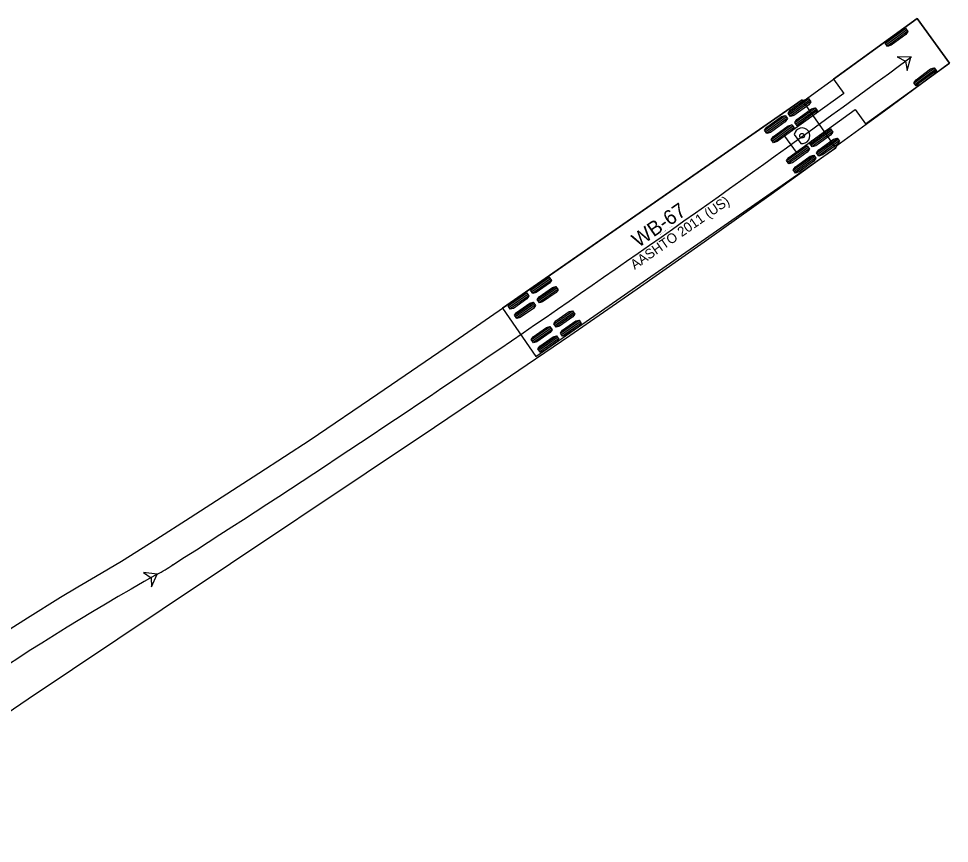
# Model space of a CAD drawing. Extents: x 2175591 to 2194071, y 76570 to 86955.
# Drawn here: x 2175817.3 to 2175952.4, y 76678.4 to 76798 of the extents above; entities that cross this region are included whole.
import ezdxf

# ---------------------------------------------------------------- set-up
doc = ezdxf.new("R2010")
doc.units = 0
doc.layers.add('C-UTIL-STRM-TEXT', color=7, linetype='Continuous')

msp = doc.modelspace()

# ---------------------------------------------------------------- linework, layer by layer
at = {"layer": 'C-UTIL-STRM-TEXT'}
for p, q in [((2175947.72, 76798.05), (2175935.56, 76789.26)), ((2175952.4, 76791.56), (2175947.72, 76798.05)), ((2175947.72, 76798.05), (2175947.72, 76798.05)), ((2175946.08, 76796.6), (2175943.13, 76794.43)), ((2175946.21, 76796.42), (2175943.26, 76794.24)), ((2175946.35, 76796.23), (2175943.4, 76794.06)), ((2175940.24, 76782.78), (2175952.4, 76791.56)), ((2175950.23, 76790.87), (2175947.28, 76788.69)), ((2175950.37, 76790.68), (2175947.42, 76788.5)), ((2175950.51, 76790.5), (2175947.55, 76788.32)), ((2175935.56, 76789.26), (2175937.06, 76787.18)), ((2175937.06, 76787.18), (2175928.47, 76780.98)), ((2175931.99, 76786.4), (2175929.02, 76784.26)), ((2175931.05, 76786.25), (2175887.52, 76756.01)), ((2175932.12, 76786.22), (2175929.15, 76784.07)), ((2175932.26, 76786.03), (2175929.29, 76783.89)), ((2175932.96, 76785.07), (2175929.98, 76782.92)), ((2175935.9, 76779.27), (2175931.05, 76786.25)), ((2175931.05, 76786.25), (2175931.05, 76786.25)), ((2175928.58, 76783.95), (2175925.61, 76781.8)), ((2175928.72, 76783.76), (2175925.75, 76781.61)), ((2175933.09, 76784.88), (2175930.12, 76782.73)), ((2175930.15, 76778.65), (2175938.74, 76784.86)), ((2175933.22, 76784.7), (2175930.25, 76782.55)), ((2175938.74, 76784.86), (2175940.24, 76782.78)), ((2175928.85, 76783.57), (2175925.88, 76781.43)), ((2175929.55, 76782.61), (2175926.58, 76780.46)), ((2175929.68, 76782.42), (2175926.71, 76780.28)), ((2175929.82, 76782.24), (2175926.85, 76780.09)), ((2175928.47, 76780.98), (2175930.15, 76778.65)), ((2175929.88, 76781.23), (2175930.83, 76779.92)), ((2175935.17, 76782), (2175932.2, 76779.85)), ((2175935.3, 76781.81), (2175932.33, 76779.67)), ((2175935.44, 76781.63), (2175932.47, 76779.48)), ((2175936.14, 76780.66), (2175933.16, 76778.52)), ((2175936.27, 76780.48), (2175933.3, 76778.33)), ((2175936.4, 76780.29), (2175933.43, 76778.14)), ((2175892.37, 76749.03), (2175935.9, 76779.27)), ((2175931.77, 76779.54), (2175928.79, 76777.39)), ((2175931.9, 76779.36), (2175928.93, 76777.21)), ((2175932.03, 76779.17), (2175929.06, 76777.02)), ((2175932.73, 76778.2), (2175929.76, 76776.06)), ((2175932.87, 76778.02), (2175929.89, 76775.87)), ((2175933, 76777.83), (2175930.03, 76775.68)), ((2175894.34, 76760.47), (2175891.63, 76758.59)), ((2175894.47, 76760.28), (2175891.76, 76758.4)), ((2175894.61, 76760.09), (2175891.9, 76758.21)), ((2175891.06, 76758.19), (2175888.35, 76756.3)), ((2175895.29, 76759.11), (2175892.58, 76757.23)), ((2175895.42, 76758.93), (2175892.71, 76757.04)), ((2175895.55, 76758.74), (2175892.84, 76756.86)), ((2175891.19, 76758), (2175888.48, 76756.12)), ((2175891.32, 76757.81), (2175888.61, 76755.93)), ((2175892, 76756.83), (2175889.29, 76754.95)), ((2175887.52, 76756.01), (2175892.37, 76749.03)), ((2175892.13, 76756.64), (2175889.42, 76754.76)), ((2175892.26, 76756.46), (2175889.55, 76754.57)), ((2175897.73, 76755.6), (2175895.02, 76753.71)), ((2175897.86, 76755.41), (2175895.15, 76753.53)), ((2175897.99, 76755.22), (2175895.28, 76753.34)), ((2175898.67, 76754.24), (2175895.96, 76752.36)), ((2175898.8, 76754.05), (2175896.09, 76752.17)), ((2175894.44, 76753.31), (2175891.73, 76751.43)), ((2175894.58, 76753.13), (2175891.86, 76751.24)), ((2175894.71, 76752.94), (2175892, 76751.06)), ((2175898.93, 76753.87), (2175896.22, 76751.98)), ((2175895.39, 76751.96), (2175892.68, 76750.08)), ((2175895.52, 76751.77), (2175892.81, 76749.89)), ((2175895.65, 76751.58), (2175892.94, 76749.7))]:
    msp.add_line(p, q, dxfattribs=at)
for points in [[(2175816.05, 76709.5), (2175818.55, 76711.09), (2175823.35, 76714.06), (2175825.87, 76715.58), (2175828.41, 76717.1), (2175832.19, 76719.3), (2175837.19, 76722.47), (2175842.18, 76725.65), (2175852.14, 76732.07), (2175859.59, 76736.93), (2175869.4, 76743.58), (2175879.18, 76750.26), (2175888.93, 76756.99), (2175931.05, 76786.25), (2175931.31, 76786.18), (2175947.72, 76798.05), (2175952.4, 76791.56), (2175942.97, 76784.62), (2175936.06, 76779.59), (2175935.9, 76779.27), (2175926.51, 76772.51), (2175916.82, 76765.62), (2175907.08, 76758.8), (2175897.3, 76752.03), (2175887.48, 76745.33), (2175877.63, 76738.69), (2175838.1, 76712.28), (2175818.66, 76699.27), (2175808.87, 76692.65)], [(2175837.37, 76717.4), (2175837.66, 76717.56), (2175837.95, 76717.73), (2175838.24, 76717.9), (2175838.52, 76718.07), (2175838.81, 76718.24), (2175839.09, 76718.41), (2175839.38, 76718.59), (2175839.66, 76718.77)]]:
    msp.add_lwpolyline(points, dxfattribs=at)
for points in [[(2175946.05, 76796.65), (2175946.38, 76796.19), (2175946.07, 76795.74), (2175943.95, 76794.18), (2175943.43, 76794.01), (2175943.09, 76794.47), (2175943.41, 76794.92), (2175945.53, 76796.48)], [(2175946.82, 76792.46), (2175944.82, 76792.5), (2175946.01, 76791.87), (2175946.26, 76790.54)], [(2175950.2, 76790.91), (2175950.54, 76790.45), (2175950.23, 76790.01), (2175948.1, 76788.44), (2175947.59, 76788.27), (2175947.25, 76788.74), (2175947.56, 76789.18), (2175949.68, 76790.75)], [(2175931.96, 76786.45), (2175932.29, 76785.99), (2175931.98, 76785.55), (2175929.84, 76784), (2175929.32, 76783.84), (2175928.98, 76784.3), (2175929.3, 76784.74), (2175931.44, 76786.29)], [(2175932.92, 76785.11), (2175933.26, 76784.65), (2175932.94, 76784.21), (2175930.8, 76782.66), (2175930.28, 76782.5), (2175929.95, 76782.97), (2175930.26, 76783.41), (2175932.4, 76784.95)], [(2175928.55, 76783.99), (2175928.89, 76783.53), (2175928.57, 76783.09), (2175926.43, 76781.54), (2175925.91, 76781.38), (2175925.58, 76781.84), (2175925.89, 76782.29), (2175928.03, 76783.83)], [(2175929.52, 76782.65), (2175929.85, 76782.19), (2175929.54, 76781.75), (2175927.4, 76780.2), (2175926.88, 76780.04), (2175926.54, 76780.51), (2175926.86, 76780.95), (2175929, 76782.49)], [(2175935.14, 76782.05), (2175935.47, 76781.58), (2175935.16, 76781.14), (2175933.02, 76779.6), (2175932.5, 76779.44), (2175932.16, 76779.9), (2175932.48, 76780.34), (2175934.62, 76781.89)], [(2175936.1, 76780.71), (2175936.44, 76780.24), (2175936.12, 76779.8), (2175933.98, 76778.26), (2175933.47, 76778.1), (2175933.13, 76778.56), (2175933.45, 76779), (2175935.59, 76780.55)], [(2175931.73, 76779.59), (2175932.07, 76779.12), (2175931.75, 76778.68), (2175929.61, 76777.14), (2175929.09, 76776.98), (2175928.76, 76777.44), (2175929.07, 76777.88), (2175931.22, 76779.43)], [(2175932.7, 76778.25), (2175933.03, 76777.79), (2175932.72, 76777.35), (2175930.58, 76775.8), (2175930.06, 76775.64), (2175929.73, 76776.1), (2175930.04, 76776.54), (2175932.18, 76778.09)], [(2175894.31, 76760.52), (2175894.64, 76760.05), (2175894.36, 76759.64), (2175892.41, 76758.29), (2175891.93, 76758.16), (2175891.6, 76758.63), (2175891.88, 76759.04), (2175893.83, 76760.39)], [(2175891.03, 76758.23), (2175891.35, 76757.76), (2175891.07, 76757.36), (2175889.12, 76756), (2175888.64, 76755.88), (2175888.32, 76756.35), (2175888.6, 76756.76), (2175890.55, 76758.11)], [(2175895.25, 76759.16), (2175895.58, 76758.69), (2175895.3, 76758.29), (2175893.35, 76756.93), (2175892.87, 76756.81), (2175892.54, 76757.28), (2175892.82, 76757.68), (2175894.78, 76759.04)], [(2175891.97, 76756.88), (2175892.29, 76756.41), (2175892.01, 76756), (2175890.06, 76754.65), (2175889.58, 76754.53), (2175889.26, 76755), (2175889.54, 76755.4), (2175891.49, 76756.76)], [(2175897.7, 76755.64), (2175898.02, 76755.17), (2175897.74, 76754.77), (2175895.79, 76753.41), (2175895.31, 76753.29), (2175894.99, 76753.76), (2175895.27, 76754.17), (2175897.22, 76755.52)], [(2175898.64, 76754.29), (2175898.96, 76753.82), (2175898.68, 76753.41), (2175896.73, 76752.06), (2175896.25, 76751.94), (2175895.93, 76752.41), (2175896.21, 76752.81), (2175898.16, 76754.17)], [(2175894.41, 76753.36), (2175894.74, 76752.89), (2175894.46, 76752.49), (2175892.51, 76751.13), (2175892.03, 76751.01), (2175891.7, 76751.48), (2175891.98, 76751.88), (2175893.93, 76753.24)], [(2175895.35, 76752.01), (2175895.68, 76751.54), (2175895.4, 76751.13), (2175893.45, 76749.78), (2175892.97, 76749.65), (2175892.64, 76750.12), (2175892.92, 76750.53), (2175894.88, 76751.88)], [(2175837.37, 76717.4), (2175835.39, 76717.68), (2175836.5, 76716.91), (2175836.58, 76715.56)]]:
    msp.add_lwpolyline(points, close=True, dxfattribs=at)
for centre, radius in [((2175946.82, 76792.46), 0.0417), ((2175931.01, 76781.04), 0.34), ((2175839.66, 76718.77), 0.0417), ((2175839.66, 76718.77), 0.0417), ((2175837.37, 76717.4), 0.0417), ((2175837.37, 76717.4), 0.0417)]:
    msp.add_circle(centre, radius, dxfattribs=at)
for centre, radius, start, end in [((2174777.14, 78378.49), 1970.69, 302.62659, 306.40847), ((2175931.01, 76781.04), 1.14, 260.8367, 170.8367), ((2176032.69, 76370.73), 397.91, 119.3977, 129.3671)]:
    msp.add_arc(centre, radius, start, end, dxfattribs=at)

# ---------------------------------------------------------------- texts
for s, height, p in [('AASHTO 2011 (US)', 1.4167, (2175906.71, 76761.57)), ('WB-67', 2.125, (2175907.25, 76764.75)), ('(c) 2019 Transoft Solutions, Inc. All rights reserved.', 0.085, (2175910.31, 76766.61))]:
    msp.add_text(s, height=height, rotation=34.7881, dxfattribs=at).set_placement(p)

doc.saveas('drawing.dxf')
